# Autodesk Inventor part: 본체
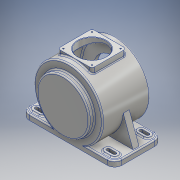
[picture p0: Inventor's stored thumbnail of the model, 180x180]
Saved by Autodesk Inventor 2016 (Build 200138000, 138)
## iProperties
Created: 2015-06
Part Number: 본체
Material: 알루미늄 6061
Document SubType Name: Modeling
Designer: Administrator
Density: 2.7 g/cm^3
Appearance: 알루미늄 - 평지
Mass: 3248.07 g
Surface Area: 2328.34 cm^2
Volume: 1202.99 cm^3
Author: Administrator
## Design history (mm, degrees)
sketch "스케치1"
  geometry: C1 r 85 at (0, 0); 1 further point
  constraints: 1 centre point, 1 coincident
  dimensions: "d0" = 170 diameter of C1
extrude "돌출1" new body sketch "스케치1" stored distance "d1" = 118; taper "d2" = 0 deg
sketch "스케치2"
  geometry: C1 r 65 at (0, 0); 1 further point
  constraints: 1 centre point, 1 coincident
  dimensions: "d3" = 130 diameter of C1
extrude "돌출2" join sketch "스케치2" distance "d4" = 62; taper "d6" = 0 deg; dims "d5" = 72, "d7" = 0
node "작업 평면1"
sketch "스케치3"
  geometry: L1 (-42.5, 42.5)-(42.5, 42.5); L2 (42.5, 42.5)-(42.5, -42.5); L3 (42.5, -42.5)-(-42.5, -42.5); L4 (-42.5, -42.5)-(-42.5, 42.5); 3 further points
  constraints: 8 end point, 2 midpoint, 2 parallel, 2 perpendicular, 1 horizontal, 1 horizontal alignment, 1 vertical alignment
  dimensions: "d9" = 85 distance of L1.start L1.end
extrude "돌출3" join sketch "스케치3" stored distance "d10" = 72; taper "d11" = 0 deg; dims "d31" = 7
fillet "모깎기1" dims "d31" = 7
sketch "스케치7"
  geometry: A1 r 7 centre (-35.5, 35.5) between (-35.5, 42.5) and (-42.5, 35.5) reference; A2 r 7 centre (-35.5, -35.5) between (-42.5, -35.5) and (-35.5, -42.5) reference; A3 r 7 centre (35.5, -35.5) between (35.5, -42.5) and (42.5, -35.5) reference; A4 r 7 centre (35.5, 35.5) between (42.5, 35.5) and (35.5, 42.5) reference; 5 further points
  constraints: 4 coincident
hole "구멍2" sketch "스케치7" at (-35.5, -35.5), (35.5, -35.5), (35.5, 35.5), (-35.5, 35.5) diameter "d41" = 3.242; stored, may be unused: countersink angle "d45" = 90 deg, drill point angle "d47" = 118 deg; dims "d42" = 10, "d43" = 4, "d44" = 2, "d46" = 13
node "작업 평면2"
sketch "스케치9"
  geometry: L1 (115, -59)-(-115, -59); L2 (-115, -59)-(-115, 59); L3 (-115, 59)-(115, 59); L4 (115, 59)-(115, -59); 3 further points
  constraints: 8 end point, 2 midpoint, 2 parallel, 1 horizontal, 1 horizontal alignment, 1 perpendicular, 1 vertical alignment
  dimensions: "d57" = 118 distance between parallel lines of L3 L1; "d58" = 230 distance between parallel lines of L2 L4
extrude "돌출4" join sketch "스케치9" distance "d59" = 14; taper "d60" = 0 deg
fillet "모깎기2" dims "d61" = 18
sketch "스케치10"
  geometry: L1 (-97, 59)-(97, 59) reference; L2 (0, 59)-(0, -59); L3 (97, -59)-(-97, -59) reference; L4 (81, 50)-(97, 50); L5 (97, 32)-(81, 32); A1 r 9 centre (97, 41) between (97, 32) and (97, 50); A2 r 9 centre (81, 41) between (81, 50) and (81, 32); 1 further point
  constraints: 6 end point, 4 point on circle, 2 centre point, 2 midpoint, 2 vertical alignment, 1 equal radius, 1 horizontal, 1 parallel
  dimensions: "d62" = 18 distance between parallel lines of L5 L4; "d63" = 16 distance of A1.centre A2.centre; "d64" = 9 radius of A1; "d65" = 18 distance from line of A1.centre L1; "d66" = 97 distance from line of L2 A1.centre
extrude "돌출5" join sketch "스케치10" distance "d68" = 3; taper "d69" = 0 deg
sketch "스케치11"
  geometry: L1 (97, 32)-(81, 32) reference; L2 (81, 50)-(97, 50) reference; L3 (51, -59)-(-51, -59) reference; L4 (-51, -59)-(-51, 59) reference; L5 (-51, 59)-(51, 59) reference; L6 (51, 59)-(51, -59) reference; L7 (81, 37)-(97, 37); L8 (81, 45)-(97, 45); A1 r 9 centre (97, 41) between (97, 32) and (97, 50) reference; A2 r 9 centre (81, 41) between (81, 50) and (81, 32) reference; A3 r 4 centre (81, 41) between (81, 45) and (81, 37); A4 r 4 centre (97, 41) between (97, 37) and (97, 45); 1 further point
  constraints: 4 end point, 4 point on circle, 2 centre point, 2 coincident, 2 horizontal, 2 tangent
  dimensions: "d70" = 8 diameter of A3; "d71" = 8 diameter of A4
extrude "돌출6" cut sketch "스케치11" stored distance "d72" = 0; taper "d73" = 0 deg
sketch "스케치12"
  geometry: L1 (84.87, -4.703)-(109, -71); L2 (-84.87, -4.703)-(-109, -71); L3 (-115, -71)-(-97, -71) reference; L4 (97, -71)-(115, -71) reference; L5 (115, -85)-(115, -71) reference; L6 (-115, -71)-(-115, -85) reference; L7 (46.733, -71)-(97, -71) reference; L8 (-97, -71)-(-46.733, -71) reference; A1 r 85 centre (0, 0) between (46.733, -71) and (-46.733, -71) reference; 1 further point
  constraints: 4 end point, 2 point on circle, 2 point on line
  dimensions: "d80" = 6 distance from line of L1.end L5; "d81" = 110 deg angle of L1 L4; "d82" = 6 distance from line of L6 L2.end; "d83" = 110 deg angle of L3 L2
feature "리브1" sketch "스케치12" dims "d84" = 1, "d85" = 15, "d86" = 0, "d87" = 0, "d88" = 1, "d89" = 1
sketch "스케치13"
  geometry: L1 (0, 0)-(77.036, 35.923); L2 (0, 0)-(85, 0); A1 r 85 centre (0, 0) between (46.733, -71) and (-46.733, -71) reference; 1 further point
  constraints: 4 end point, 2 point on circle, 1 horizontal
  dimensions: "d90" = 25 deg angle of L2 L1
node "작업 평면3"
sketch "스케치14"
  geometry: 2 further points
  constraints: 1 coincident, 1 other
feature "엠보싱1" sketch "스케치14" dims "d91" = 0.5, "d92" = 0
fillet "모깎기3" dims "d93" = 3
sketch "스케치16"
  geometry: L1 (-72, -62)-(-72, 62) reference; L2 (62, -65)-(62, 65) reference; L3 (-72, 0)-(62, 0); L4 (-64.5, 0)-(-64.5, 12); L5 (-62, -65)-(-62, 65) reference; L6 (-61.5, 15)-(-61.5, 15); L7 (-61.5, 15)-(-61.5, 23.2); L8 (-61.2, 23.5)-(-48.5, 23.5); L9 (-47.5, 24.5)-(-47.5, 29.368); L10 (-47.5, 29.368)-(-49.268, 30.192); L11 (-51, 32.911)-(-51, 74); L12 (-48, 77)-(48, 77); L13 (35.5, 72.756)-(-35.5, 72.756) reference; L14 (51, 74)-(51, 47.5); L15 (51, 47.5)-(62, 47.5); L16 (59, 82)-(59, -74) reference; L17 (-48.5, 23.5)-(-47.5, 24.5); A1 r 0.3 centre (-61.2, 23.2) between (-61.2, 23.5) and (-61.5, 23.2); A2 r 3 centre (-61.5, 12) between (-61.5, 15) and (-64.5, 12); A3 r 3 centre (-48, 32.911) between (-51, 32.911) and (-49.268, 30.192); A4 r 3 centre (-48, 74) between (-48, 77) and (-51, 74); A5 r 3 centre (48, 74) between (51, 74) and (48, 77); 3 further points
  constraints: 24 end point, 10 point on circle, 10 tangent, 6 point on line, 5 centre point, 5 perpendicular, 3 parallel, 2 midpoint, 1 equal radius, 1 vertical
  dimensions: "d97" = 30 diameter of L6 L3; "d98" = 3 distance between parallel lines of L7 L4; "d99" = 14 distance between parallel lines of L9 L7; "d100" = 115 deg angle of L10 L11; "d101" = 154 diameter of L12 L3; "d104" = 102 distance between parallel lines of L14 L11; "d105" = 95 diameter of L15 L3; "d106" = 8 distance between parallel lines of L16 L14; "d107" = 62 diameter of point (-51, 31) L3; "d108" = 47 diameter of L8 L3; "d109" = 3.5 distance between parallel lines of L9 L11; "d110" = 0.3 radius of A1; "d111" = 3 radius of A2; "d112" = 1 distance of L8.end point (-47.5, 23.5); "d113" = 1 distance of L9.start point (-47.5, 23.5) (= d112); "d114" = 3 radius of A3; "d115" = 3 radius of A5
revolve "회전2" sketch "스케치16" stored, may be unused: angle "d116" = 90 deg
sketch "스케치18"
  geometry: 2 further points
  constraints: 1 coincident
hole "구멍5" sketch "스케치18" at (0, 0) diameter "d125" = 70; stored, may be unused: countersink angle "d129" = 90 deg, drill point angle "d131" = 0 deg; dims "d126" = 8, "d127" = 4, "d128" = 2, "d130" = 50
sketch "스케치17"
  geometry: A1 r 55 centre (0, 0) between (0, -55) and (55, 0); 3 further points
  constraints: 4 point on circle, 2 horizontal alignment, 2 vertical alignment, 1 centre point, 1 coincident
  dimensions: "d117" = 110 diameter of A1
hole "구멍4" sketch "스케치17" at (0, -55), (55, 0), (0, 55), (-55, 0) diameter "d118" = 3.242; stored, may be unused: countersink angle "d122" = 90 deg, drill point angle "d124" = 118 deg; dims "d119" = 8, "d120" = 4, "d121" = 2, "d123" = 50
chamfer "모따기2" distance "d132" = 1; stored, may be unused: second distance "d133" = 2, angle "d134" = 45 deg
fillet "모깎기4" dims "d135" = 3
node "솔리드1"
pattern_linear "직사각형 패턴1" dims "d76" = 82, "d79" = 178
mirror "대칭1"
node "절단 모서리 투영1"
other parameters: "d8" = 88, "d56" = -85
